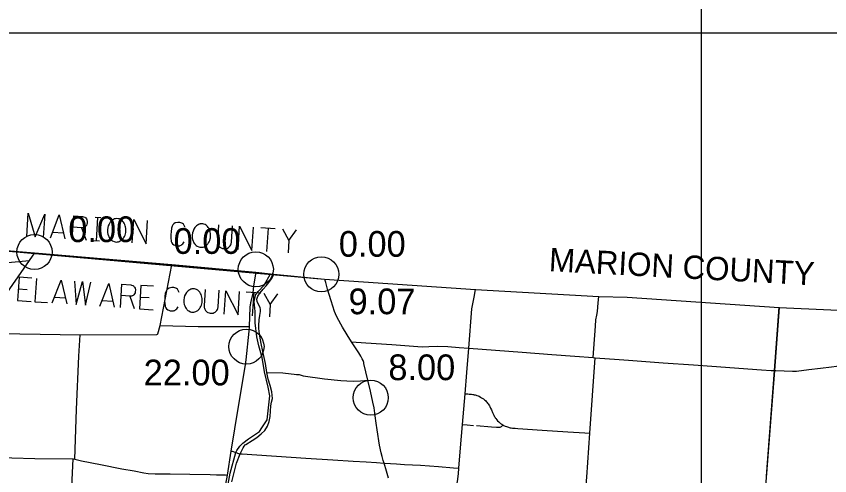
# Model space of a CAD drawing. Extents: x 1659811 to 1934326, y 644115 to 934867.
# Drawn here: x 1765018 to 1799814, y 881041 to 900699 of the extents above; entities that cross this region are included whole.
import ezdxf

# ---------------------------------------------------------------- set-up
doc = ezdxf.new("R2010")
doc.units = 0
for name, color, linetype in [('Default', 7, 'Continuous'), ('GM_X_Adjacent_County_Text', 7, 'Continuous'), ('GM_X_County', 7, 'Continuous'), ('GM_X_County_Road', 7, 'Continuous'), ('GM_X_State_Route', 7, 'Continuous'), ('GM_X_Township', 7, 'Continuous'), ('GM_X_Township_Road', 7, 'Continuous'), ('SC_Scratch1', 7, 'Continuous')]:
    doc.layers.add(name, color=color, linetype=linetype)

msp = doc.modelspace()

# ---------------------------------------------------------------- linework, layer by layer
at = {"layer": 'Default'}
for centre in [(1765798, 890612), (1765798, 890612), (1775265, 889876), (1775265, 889876), (1778064, 889660), (1778064, 889660), (1774865, 886568), (1780183, 884380)]:
    msp.add_circle(centre, 750, dxfattribs=at)
at = {"layer": 'GM_X_Adjacent_County_Text'}
for p, q in [((1768386, 892101), (1768638, 892086)), ((1768450, 891095), (1768512, 892093)), ((1767814, 891648), (1768002, 891123)), ((1775474, 891658), (1776095, 891619)), ((1775789, 891638), (1775726, 890640)), ((1767034, 891421), (1766571, 891450)), ((1760161, 891042), (1775269, 889747)), ((1760161, 891042), (1778209, 889456)), ((1768324, 891103), (1768575, 891088)), ((1776678, 891101), (1776646, 890583)), ((1765102, 889039), (1765487, 889012)), ((1769875, 888722), (1770062, 888197)), ((1774859, 888904), (1775480, 888867)), ((1775173, 888885), (1775114, 887887)), ((1767115, 888632), (1766652, 888664)), ((1769148, 888494), (1768684, 888525)), ((1770320, 888685), (1770705, 888660)), ((1775874, 888362), (1775843, 887843))]:
    msp.add_line(p, q, dxfattribs=at)
for points in [[(1765464, 891282), (1765526, 892280), (1765825, 891260), (1766233, 892236), (1766171, 891238)], [(1766477, 891219), (1766854, 892197), (1767098, 891180)], [(1767412, 891160), (1767475, 892158), (1767852, 892135), (1767891, 892124), (1767945, 892105), (1767967, 892088), (1767990, 892071), (1768019, 892030), (1768040, 891989), (1768052, 891925), (1768046, 891831), (1768036, 891800), (1768017, 891754), (1767983, 891700), (1767950, 891679), (1767925, 891665), (1767909, 891658), (1767885, 891651), (1767814, 891648), (1767444, 891671)], [(1769266, 892038), (1769242, 892032), (1769218, 892026), (1769177, 892004), (1769153, 891990), (1769111, 891961), (1769078, 891932), (1769061, 891917), (1769036, 891887), (1768991, 891811), (1768955, 891734), (1768935, 891665), (1768921, 891563), (1768922, 891452), (1768940, 891372), (1768960, 891308), (1768974, 891276), (1768995, 891235), (1769024, 891194), (1769046, 891169), (1769068, 891143), (1769098, 891118), (1769136, 891092), (1769204, 891056), (1769243, 891046), (1769322, 891041), (1769354, 891047), (1769386, 891053), (1769426, 891066), (1769467, 891087), (1769491, 891101), (1769516, 891115), (1769541, 891138), (1769566, 891168), (1769584, 891190), (1769601, 891213), (1769618, 891235), (1769645, 891281), (1769672, 891335), (1769691, 891396), (1769703, 891451), (1769703, 891459), (1769706, 891514), (1769709, 891561), (1769705, 891624), (1769694, 891688), (1769681, 891736), (1769661, 891793), (1769640, 891841), (1769604, 891891), (1769574, 891924), (1769545, 891958), (1769515, 891983), (1769469, 892010), (1769423, 892029), (1769376, 892039), (1769321, 892043), (1769266, 892038)], [(1769982, 891000), (1770044, 891998), (1770571, 890963), (1770634, 891961)], [(1772240, 891663), (1772206, 891752), (1772170, 891801), (1772133, 891835), (1772102, 891853), (1772017, 891874), (1771930, 891880), (1771818, 891855), (1771753, 891812), (1771719, 891774), (1771684, 891721), (1771655, 891636), (1771637, 891480), (1771630, 891362), (1771625, 891283), (1771628, 891212), (1771644, 891085), (1771650, 891061), (1771678, 891004), (1771707, 890963), (1771760, 890920), (1771806, 890901), (1771868, 890882), (1771939, 890877), (1772010, 890880), (1772034, 890887), (1772066, 890901), (1772100, 890930), (1772141, 890967), (1772176, 891012), (1772202, 891050)], [(1772889, 891812), (1772864, 891805), (1772840, 891799), (1772800, 891778), (1772775, 891763), (1772734, 891734), (1772700, 891705), (1772684, 891690), (1772658, 891660), (1772614, 891584), (1772578, 891508), (1772557, 891438), (1772543, 891336), (1772544, 891226), (1772563, 891146), (1772582, 891081), (1772596, 891049), (1772617, 891008), (1772646, 890967), (1772668, 890942), (1772691, 890917), (1772720, 890891), (1772758, 890865), (1772827, 890829), (1772866, 890819), (1772944, 890814), (1772976, 890820), (1773008, 890826), (1773049, 890839), (1773089, 890860), (1773114, 890874), (1773138, 890889), (1773163, 890911), (1773189, 890941), (1773206, 890963), (1773223, 890986), (1773241, 891009), (1773267, 891054), (1773294, 891108), (1773314, 891170), (1773325, 891224), (1773326, 891232), (1773329, 891287), (1773332, 891334), (1773328, 891398), (1773316, 891461), (1773303, 891510), (1773283, 891566), (1773263, 891615), (1773226, 891664), (1773197, 891698), (1773167, 891731), (1773138, 891757), (1773092, 891783), (1773046, 891802), (1772999, 891813), (1772944, 891816), (1772889, 891812)], [(1773667, 891771), (1773623, 891071), (1773627, 891000), (1773633, 890976), (1773646, 890936), (1773660, 890903), (1773682, 890871), (1773696, 890854), (1773704, 890846), (1773734, 890820), (1773756, 890803), (1773787, 890785), (1773833, 890766), (1773880, 890756), (1773927, 890753), (1773974, 890758), (1774006, 890763), (1774055, 890784), (1774096, 890805), (1774129, 890835), (1774163, 890872), (1774189, 890918), (1774208, 890956), (1774220, 891034), (1774264, 891734)], [(1774508, 890716), (1774571, 891714), (1775098, 890679), (1775160, 891677)], [(1776409, 891599), (1776678, 891101), (1777007, 891562)], [(1765678, 889497), (1765136, 889534), (1765067, 888536), (1765649, 888496)], [(1765881, 889483), (1765812, 888485), (1766354, 888448)], [(1766557, 888434), (1766940, 889410), (1767178, 888391)], [(1767506, 889371), (1767587, 888363), (1767852, 889348), (1767980, 888336), (1768205, 889323)], [(1768590, 888295), (1768971, 889271), (1769210, 888253)], [(1769473, 888235), (1769538, 889233), (1769915, 889208), (1769954, 889198), (1770008, 889179), (1770030, 889161), (1770053, 889144), (1770082, 889103), (1770103, 889062), (1770114, 888998), (1770108, 888904), (1770098, 888873), (1770080, 888827), (1770044, 888774), (1770012, 888752), (1769987, 888738), (1769971, 888731), (1769947, 888725), (1769875, 888722), (1769506, 888746)], [(1770894, 889145), (1770352, 889180), (1770288, 888182), (1770869, 888145)], [(1771979, 888880), (1771945, 888969), (1771909, 889018), (1771871, 889052), (1771841, 889070), (1771755, 889091), (1771669, 889096), (1771557, 889071), (1771491, 889028), (1771457, 888991), (1771423, 888938), (1771394, 888853), (1771376, 888696), (1771369, 888578), (1771364, 888500), (1771367, 888428), (1771383, 888301), (1771390, 888277), (1771418, 888220), (1771447, 888179), (1771499, 888136), (1771545, 888118), (1771607, 888098), (1771678, 888094), (1771749, 888097), (1771773, 888104), (1771806, 888117), (1771839, 888147), (1771881, 888184), (1771915, 888229), (1771941, 888267)], [(1772529, 889036), (1772505, 889029), (1772481, 889023), (1772441, 889001), (1772416, 888987), (1772375, 888958), (1772342, 888929), (1772325, 888914), (1772299, 888884), (1772255, 888808), (1772219, 888731), (1772199, 888661), (1772185, 888559), (1772186, 888449), (1772205, 888369), (1772225, 888305), (1772239, 888272), (1772260, 888232), (1772289, 888190), (1772311, 888165), (1772333, 888140), (1772363, 888115), (1772401, 888089), (1772470, 888053), (1772509, 888043), (1772587, 888038), (1772619, 888044), (1772651, 888050), (1772692, 888063), (1772732, 888085), (1772757, 888099), (1772781, 888113), (1772806, 888135), (1772832, 888165), (1772849, 888188), (1772866, 888211), (1772883, 888233), (1772910, 888279), (1772937, 888333), (1772956, 888395), (1772967, 888449), (1772968, 888457), (1772971, 888512), (1772974, 888559), (1772970, 888622), (1772958, 888686), (1772945, 888734), (1772925, 888791), (1772904, 888839), (1772868, 888889), (1772838, 888922), (1772809, 888956), (1772779, 888981), (1772733, 889008), (1772687, 889026), (1772640, 889037), (1772585, 889040), (1772529, 889036)], [(1773097, 889009), (1773055, 888310), (1773058, 888238), (1773065, 888214), (1773078, 888174), (1773092, 888142), (1773114, 888109), (1773129, 888092), (1773136, 888084), (1773166, 888058), (1773189, 888041), (1773219, 888024), (1773265, 888005), (1773312, 887995), (1773359, 887992), (1773407, 887997), (1773439, 888003), (1773487, 888023), (1773528, 888045), (1773561, 888074), (1773595, 888112), (1773621, 888157), (1773640, 888196), (1773652, 888274), (1773694, 888974)], [(1773918, 887958), (1773978, 888957), (1774507, 887923), (1774567, 888921)], [(1775604, 888859), (1775874, 888362), (1776201, 888824)]]:
    msp.add_lwpolyline(points, dxfattribs=at)
at = {"layer": 'GM_X_County'}
msp.add_lwpolyline([(1760161, 891042), (1765804, 890577), (1771666, 890080), (1775269, 889747), (1775894, 889674), (1776032, 889658), (1778209, 889456), (1784657, 889014), (1789933, 888711), (1791146, 888682), (1797651, 888237), (1803655, 887971)], dxfattribs=at)
at = {"layer": 'GM_X_County_Road'}
for points in [[(1783164, 876512), (1783184, 876554), (1783209, 876711), (1783243, 876961), (1783384, 877811), (1783523, 878729), (1783651, 879411), (1783765, 880071), (1783893, 880796), (1783932, 881116), (1783954, 881366), (1784027, 882233), (1784112, 883231), (1784194, 884219), (1784219, 884544), (1784290, 885451), (1784371, 886499), (1784505, 888183), (1784615, 888751), (1784662, 889026)], [(1789695, 886094), (1789719, 886480), (1789799, 887439), (1789813, 887710), (1789851, 887912), (1789876, 888066), (1789915, 888443), (1789938, 888712)], [(1779364, 886770), (1779967, 886729), (1781087, 886653), (1782198, 886565), (1782396, 886560), (1782670, 886574), (1783048, 886584), (1783473, 886564), (1783964, 886527), (1784371, 886499), (1786660, 886325), (1787926, 886227), (1788905, 886151), (1789695, 886094), (1789778, 886088), (1790812, 886013), (1791205, 885983), (1792690, 885877), (1793992, 885783), (1794775, 885730), (1796902, 885573), (1797304, 885549), (1797451, 885547), (1797502, 885545)], [(1797502, 885545), (1798225, 885516), (1798393, 885518), (1798918, 885581), (1799416, 885645), (1799891, 885700), (1800108, 885729), (1800227, 885756), (1800345, 885789), (1800404, 885808), (1800482, 885836), (1801245, 886152), (1801314, 886180), (1802090, 886513), (1802428, 886671)], [(1788586, 869035), (1788657, 870095), (1788840, 872922), (1788956, 874843), (1789001, 875254), (1789063, 876180), (1789105, 876736), (1789110, 876852), (1789151, 877401), (1789258, 879010), (1789428, 880980), (1789558, 882861), (1789778, 886088)], [(1774211, 882090), (1774252, 882089), (1774404, 882033)], [(1759969, 881997), (1762841, 881858), (1765814, 881778), (1767451, 881759), (1767471, 881758), (1767516, 881753), (1767813, 881684), (1768617, 881522), (1769536, 881337), (1770062, 881247), (1770477, 881159), (1770666, 881130), (1770953, 881125), (1771606, 881121), (1772443, 881104), (1773313, 881088), (1773587, 881081), (1773877, 881076), (1773962, 881074), (1774048, 881064)], [(1774404, 882033), (1774406, 882032), (1774523, 881989), (1774565, 881978), (1774598, 881976), (1774681, 881977), (1777408, 881796), (1778560, 881723), (1779427, 881668), (1779984, 881633), (1780423, 881605), (1780749, 881582)]]:
    msp.add_lwpolyline(points, dxfattribs=at)
at = {"layer": 'GM_X_State_Route'}
for points in [[(1759881, 881868), (1759956, 881980), (1759969, 881997), (1763443, 887141), (1764744, 889038), (1765591, 890255), (1765808, 890573)], [(1760071, 889009), (1760118, 889022), (1762397, 889618), (1763225, 889831), (1763889, 890004), (1764355, 890118), (1764820, 890175), (1765591, 890255)], [(1773882, 880140), (1774048, 881064), (1774211, 882090), (1774530, 884003), (1774667, 884846), (1774801, 885624), (1774814, 885707), (1774851, 886003), (1774976, 887219), (1774992, 887423), (1775028, 888248), (1775030, 888289), (1775035, 888331), (1775040, 888372), (1775048, 888413), (1775057, 888454), (1775067, 888494), (1775128, 888732), (1775139, 888776), (1775154, 888865), (1775187, 889163), (1775276, 889757)], [(1780935, 880943), (1780851, 881229), (1780749, 881582), (1780714, 881694), (1780668, 881862), (1780620, 882022), (1780562, 882353), (1780462, 883009), (1780418, 883294), (1780375, 883601), (1780321, 883942), (1780275, 884187), (1780166, 884660), (1780054, 885130), (1779891, 885844), (1779879, 885886), (1779851, 885966), (1779818, 886043), (1779756, 886154), (1779666, 886298), (1779364, 886770), (1779176, 887069), (1778977, 887392), (1778738, 887817), (1778667, 887962), (1778627, 888061), (1778487, 888517), (1778336, 889030), (1778262, 889312), (1778237, 889390), (1778211, 889454)]]:
    msp.add_lwpolyline(points, dxfattribs=at)
at = {"layer": 'GM_X_Township'}
for points in [[(1774059, 880530), (1774167, 881144), (1774406, 882032), (1774456, 882123), (1774578, 882303), (1774707, 882427), (1774948, 882624), (1775424, 882934), (1775526, 883091), (1775753, 883439), (1775862, 884465), (1775797, 884834), (1775636, 885483), (1775537, 886105), (1775391, 886594), (1775307, 886986), (1775234, 887582), (1775230, 888073), (1775193, 888494), (1775219, 888624), (1775271, 888791), (1775360, 888928), (1775618, 889192), (1775894, 889674)], [(1797651, 888237), (1797451, 885547), (1797071, 880600), (1796711, 876185), (1796651, 875449), (1796250, 870609), (1795573, 862604)]]:
    msp.add_lwpolyline(points, dxfattribs=at)
at = {"layer": 'GM_X_Township_Road'}
for points in [[(1763443, 887141), (1767751, 887076), (1767754, 887076), (1771026, 887079), (1771060, 887099), (1771076, 887115), (1771171, 887463), (1771666, 890061)], [(1774598, 881976), (1774720, 882234), (1774760, 882299), (1774813, 882356), (1774843, 882381), (1775103, 882554), (1775313, 882683), (1775499, 882831), (1775649, 882983), (1775766, 883156), (1775837, 883357), (1775874, 883577), (1775887, 883810), (1775907, 884030), (1775933, 884182), (1775979, 884346), (1775947, 884626), (1775885, 884907), (1775798, 885171), (1775741, 885463), (1775674, 885840), (1775571, 886351), (1775497, 886692), (1775435, 887014), (1775403, 887209), (1775389, 887360), (1775389, 887468), (1775413, 887707), (1775432, 887898), (1775464, 888072), (1775469, 888156), (1775448, 888237), (1775365, 888393), (1775328, 888495), (1775314, 888590), (1775354, 888724), (1775454, 888867), (1775584, 889017), (1775702, 889168), (1775820, 889307), (1775910, 889426), (1775960, 889506), (1776017, 889615), (1776026, 889659)], [(1797103, 881017), (1797451, 885547), (1797658, 888259)], [(1771171, 887463), (1772796, 887430), (1772896, 887428), (1774620, 887429), (1774992, 887423)], [(1767516, 881753), (1767592, 883879), (1767693, 886154), (1767751, 887076)], [(1775741, 885463), (1776426, 885437), (1776777, 885403), (1776902, 885381), (1777004, 885378), (1777125, 885372), (1777289, 885315), (1778196, 885185), (1778905, 885114), (1779153, 885103), (1779444, 885093), (1779746, 885100), (1779909, 885109), (1779987, 885117), (1780054, 885130)], [(1784219, 884544), (1784275, 884542), (1784330, 884538), (1784387, 884534), (1784447, 884529), (1784491, 884526), (1784544, 884519), (1784576, 884515), (1784610, 884507), (1784645, 884498), (1784687, 884486), (1784724, 884474), (1784769, 884457), (1784812, 884440), (1784875, 884406), (1784925, 884377), (1784951, 884362), (1785001, 884324), (1785043, 884292), (1785085, 884253), (1785121, 884218), (1785146, 884188), (1785177, 884152), (1785205, 884114), (1785227, 884081), (1785255, 884038), (1785278, 883997), (1785307, 883937), (1785343, 883856), (1785390, 883751), (1785417, 883692), (1785443, 883636), (1785467, 883591), (1785486, 883555), (1785505, 883524), (1785531, 883487), (1785569, 883438), (1785608, 883393), (1785656, 883346), (1785690, 883316), (1785736, 883281), (1785782, 883246), (1785833, 883216), (1785864, 883197), (1785902, 883180), (1785935, 883164), (1785984, 883144), (1786034, 883126), (1786072, 883114), (1786104, 883105), (1786151, 883095), (1786182, 883089), (1786246, 883080), (1786362, 883072), (1786468, 883065)], [(1784112, 883231), (1784306, 883215), (1784581, 883194)], [(1784699, 883186), (1785349, 883138), (1785566, 883125), (1785579, 883124)], [(1785579, 883124), (1785689, 883117), (1785701, 883119), (1785723, 883121), (1785749, 883131), (1785773, 883145), (1785790, 883160), (1785812, 883183), (1785833, 883216)], [(1786468, 883065), (1787514, 882996), (1788607, 882920), (1789343, 882874), (1789558, 882861)], [(1767271, 876519), (1767296, 877988), (1767372, 879961), (1767451, 881759)], [(1774238, 880775), (1774441, 881584), (1774598, 881976)], [(1780749, 881582), (1781033, 881565), (1781283, 881552), (1781619, 881527), (1782312, 881487), (1783082, 881429), (1783715, 881383), (1783954, 881366)]]:
    msp.add_lwpolyline(points, dxfattribs=at)
at = {"layer": 'SC_Scratch1'}
for points in [[(1659811, 738617), (1659811, 934867), (1794311, 934867), (1794311, 738617)], [(1729596, 899996), (1925846, 899996), (1925846, 765496), (1729596, 765496)]]:
    msp.add_lwpolyline(points, close=True, dxfattribs=at)

# ---------------------------------------------------------------- texts
at = {"layer": 'Default'}
for s, p in [('0.00', (1767243, 891037)), ('0.00', (1771748, 890533)), ('0.00', (1778814, 890410)), ('9.07', (1779232, 887951)), ('22.00', (1770467, 884906)), ('8.00', (1780933, 885130))]:
    msp.add_text(s, height=1100, dxfattribs=at).set_placement(p)
at = {"layer": 'GM_X_Adjacent_County_Text'}
msp.add_text('MARION COUNTY', height=1000, rotation=356.9158, dxfattribs=at).set_placement((1787785, 889795))

doc.saveas('drawing.dxf')
